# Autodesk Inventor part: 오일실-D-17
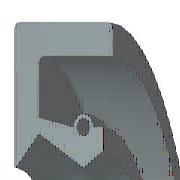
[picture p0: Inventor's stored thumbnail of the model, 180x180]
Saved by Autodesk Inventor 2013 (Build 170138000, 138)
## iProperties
IsCustomPart: 0
Company: 한국ATC센터
Created: 2014-12
Part Number: 오일실-D-17
Material: 고무
Description: 오일-실
Document SubType Name: Modeling
Standard: KS B 2804
Designer: KYOUNG IL JANG
Standards Organization: KS
Language: ko-KR
Size Designation: D - 17 30 8
Categories: <MemberInstance><Categories><Category DisplayName="샤프트 부품" InternalName="7f7aeb1f-a693-4053-b835-cee3144e0d98" Mnemonic="SHFT"><Category DisplayName="실링" Intern
Density: 0.93 g/cm^3
Mass: 2.05797 g
Surface Area: 29.3036 cm^2
Volume: 2.21288 cm^3
Author: KYOUNG IL JANG
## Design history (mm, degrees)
revolve "본체" stored, may be unused: angle "d17" = 90 deg
revolve "스프링1" stored, may be unused: angle "d18" = 90 deg
body "Solid1"
sketch "스케치1"
  geometry: L1 (0, 15)-(8, 15); L2 (8, 13.25)-(1.75, 13.25); L3 (1.75, 10.25)-(4.9, 8.5); L4 (4.9, 8.5)-(0, 8.5); L5 (0, 0)-(9.586, 0) reference; L6 (4.9, 8.5)-(6.3, 9.375); L7 (0, 18)-(0, -3) reference; L8 (-1.941, 0)-(11.507, 0) reference; L9 (4.2, 10.6)-(1.75, 11.21); L10 (1.75, 11.21)-(1.75, 13.25); L11 (0, 15)-(0, 8.588); L12 (4.9, 8.5)-(0, 8.5); L13 (1.75, 10.25)-(0.152, 8.528); L14 (8, 15)-(8, 13.25); L15 (5.6, 10.6)-(6.3, 10.6); L16 (6.3, 10.6)-(6.3, 9.375); C1 r 0.455 at (4.9, 10.6); A1 r 0.7 centre (4.9, 10.6) between (5.6, 10.6) and (4.2, 10.6); A2 r 0.088 centre (0.088, 8.588) between (0, 8.588) and (0.152, 8.528); 1 further point
  constraints: 28 end point, 5 horizontal alignment, 5 point on line, 4 point on circle, 4 vertical alignment, 3 centre point, 3 tangent, 2 collinear, 2 horizontal, 2 perpendicular, 1 coincident, 1 parallel
  dimensions: "d0" = 30 diameter of L1 L5 (= SD2); "d1" = 1.75 distance of L1.end L2.start (= SD); "d2" = 0.91 diameter of C1 (= SPDI); "d3" = 1.4 diameter of A1 (= SPDA); "d4" = 17 diameter of L3.end L5 (= NND); "d5" = 20.5 diameter of L3.start L5 (= TKDM); "d7" = 22.42 diameter of L9.end L5 (= TKDM + 0.24 x SWDT); "d8" = 1.75 distance between parallel lines of L11 L10 (= SD); "d9" = 4.9 distance from line of L11 C1.centre (= SPDST); "d10" = 21.2 diameter of C1.centre L5 (= HLDM); "d11" = 0.0875 radius of A2 (= 0.25 x LAB); "d12" = 6.3 distance between parallel lines of L11 L16 (= SDI); "d13" = 18.75 diameter of L6.end L5 (= ABDM); "d14" = 8 distance from line of L11 L1.end (= SWDT)
fillet "모깎기1" dims "d6" = 0.3 (= RR)
other parameters: "SD2" = 30 [user parameter; used in 1 equation term], "SWDT" = 8 [user parameter; used in 2 equation terms], "RR" = 0.3 [user parameter; used in 1 equation term], "SD" = 1.75 [user parameter; used in 2 equation terms], "NND" = 17 [user parameter; used in 1 equation term], "SPDA" = 1.4 [user parameter; used in 1 equation term], "SPDI" = 0.91 [user parameter; used in 1 equation term], "TKDM" = 20.5 [user parameter; used in 2 equation terms], "HLDM" = 21.2 [user parameter; used in 1 equation term], "ABDM" = 18.75 [user parameter; used in 1 equation term], "SDI" = 6.3 [user parameter; used in 1 equation term], "SPDST" = 4.9 [user parameter; used in 1 equation term], "LAB" = 0.35 [user parameter; used in 1 equation term], "d15" = 0, "d16" = 0, "d19" = 0
